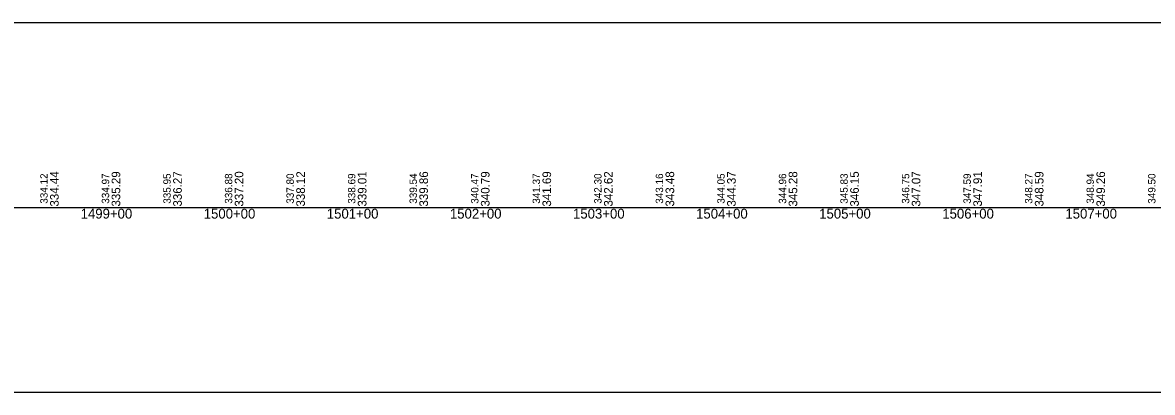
# Model space of a CAD drawing. Extents: x -3627 to 47473, y 2850 to 4350.
# Drawn here: x 37306 to 38224, y 2850 to 3150 of the extents above; entities that cross this region are included whole.
import ezdxf

# ---------------------------------------------------------------- set-up
doc = ezdxf.new("R2010")
doc.units = 0
for name, color, linetype in [('RD_DDB_StaTX', 7, 'Continuous'), ('RD_DDB_StripGrade', 7, 'Continuous'), ('RD_GPK_Profile_Cell', 7, 'Continuous'), ('RD_SHT_ShtClip', 7, 'Continuous')]:
    doc.layers.add(name, color=color, linetype=linetype)

msp = doc.modelspace()

# ---------------------------------------------------------------- linework, layer by layer
at = {"layer": 'RD_GPK_Profile_Cell'}
msp.add_line((1000, 3000), (46705.077602, 3000), dxfattribs=at)
at = {"layer": 'RD_SHT_ShtClip'}
msp.add_lwpolyline([(36933.33, 3150), (38473.33, 3150), (38473.33, 2850), (36933.33, 2850)], close=True, dxfattribs=at)

# ---------------------------------------------------------------- texts
at = {"layer": 'RD_DDB_StaTX'}
for s, p in [('1499+00', (37353.125471, 2991)), ('1500+00', (37453.125471, 2991)), ('1501+00', (37553.125471, 2991)), ('1502+00', (37653.125471, 2991)), ('1503+00', (37753.125471, 2991)), ('1504+00', (37853.125471, 2991)), ('1505+00', (37953.125471, 2991)), ('1506+00', (38053.125471, 2991)), ('1507+00', (38153.125471, 2991))]:
    msp.add_text(s, height=8, dxfattribs=at).set_placement(p)
at = {"layer": 'RD_DDB_StripGrade'}
for s, height, p in [('334.44', 7, (37335.33, 3000.75)), ('335.29', 7, (37385.33, 3000.75)), ('336.27', 7, (37435.33, 3000.75)), ('337.20', 7, (37485.33, 3000.75)), ('338.12', 7, (37535.33, 3000.75)), ('339.01', 7, (37585.33, 3000.75)), ('339.86', 7, (37635.33, 3000.75)), ('340.79', 7, (37685.33, 3000.75)), ('341.69', 7, (37735.33, 3000.75)), ('342.62', 7, (37785.33, 3000.75)), ('343.48', 7, (37835.33, 3000.75)), ('344.37', 7, (37885.33, 3000.75)), ('345.28', 7, (37935.33, 3000.75)), ('346.15', 7, (37985.33, 3000.75)), ('347.07', 7, (38035.33, 3000.75)), ('347.91', 7, (38085.33, 3000.75)), ('348.59', 7, (38135.33, 3000.75)), ('349.26', 7, (38185.33, 3000.75)), ('334.12', 6, (37326.33, 3003.073688)), ('334.97', 6, (37376.33, 3003.073688)), ('335.95', 6, (37426.33, 3003.073688)), ('336.88', 6, (37476.33, 3003.073688)), ('337.80', 6, (37526.33, 3003.073688)), ('338.69', 6, (37576.33, 3003.073688)), ('339.54', 6, (37626.33, 3003.073688)), ('340.47', 6, (37676.33, 3003.073688)), ('341.37', 6, (37726.33, 3003.073688)), ('342.30', 6, (37776.33, 3003.073688)), ('343.16', 6, (37826.33, 3003.073688)), ('344.05', 6, (37876.33, 3003.073688)), ('344.96', 6, (37926.33, 3003.073688)), ('345.83', 6, (37976.33, 3003.073688)), ('346.75', 6, (38026.33, 3003.073688)), ('347.59', 6, (38076.33, 3003.073688)), ('348.27', 6, (38126.33, 3003.073688)), ('348.94', 6, (38176.33, 3003.073688)), ('349.50', 6, (38226.33, 3003.073688))]:
    msp.add_text(s, height=height, rotation=90, dxfattribs=at).set_placement(p)

doc.saveas('drawing.dxf')
